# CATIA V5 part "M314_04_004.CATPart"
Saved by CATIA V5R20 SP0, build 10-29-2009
Part number: M314_04_004
Source: Unknown
Property "ARTICLENO": "M314-04-004"
Property "B": "35.000"
Property "BOMINFO": "M314-04-004"
Property "CODE": "M314-04-004"
Property "D": "8.000"
Property "FINALFORCE": "98.0 (10)"
Property "INITIALFORCE": "19.6 (2)"
Property "K": "10.000"
Property "L": "50.000"
Property "LINA": "M314-04-004"
Property "M": "M16x2.0"
Property "NB": "M314-04-004"
Property "NBSYN": "$CODE."
Property "NN": "M314-04"
Property "NT": "Spring Plunger"
Property "SUPPLIER": "CF"
Property "SW": "5.000"
Bounding box of the stored display mesh (mm): x -8 to 8, y 0 to 60, z -8 to 8
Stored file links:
  C:\Users\Utente\Desktop\3D files M314\M314_04_004.CATPart
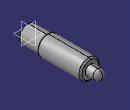
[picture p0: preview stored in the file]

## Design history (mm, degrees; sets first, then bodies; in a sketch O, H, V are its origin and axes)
Body1 "Geometry.1" (main body)
  Solid1 "M314_04_004.catpart": solid without history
